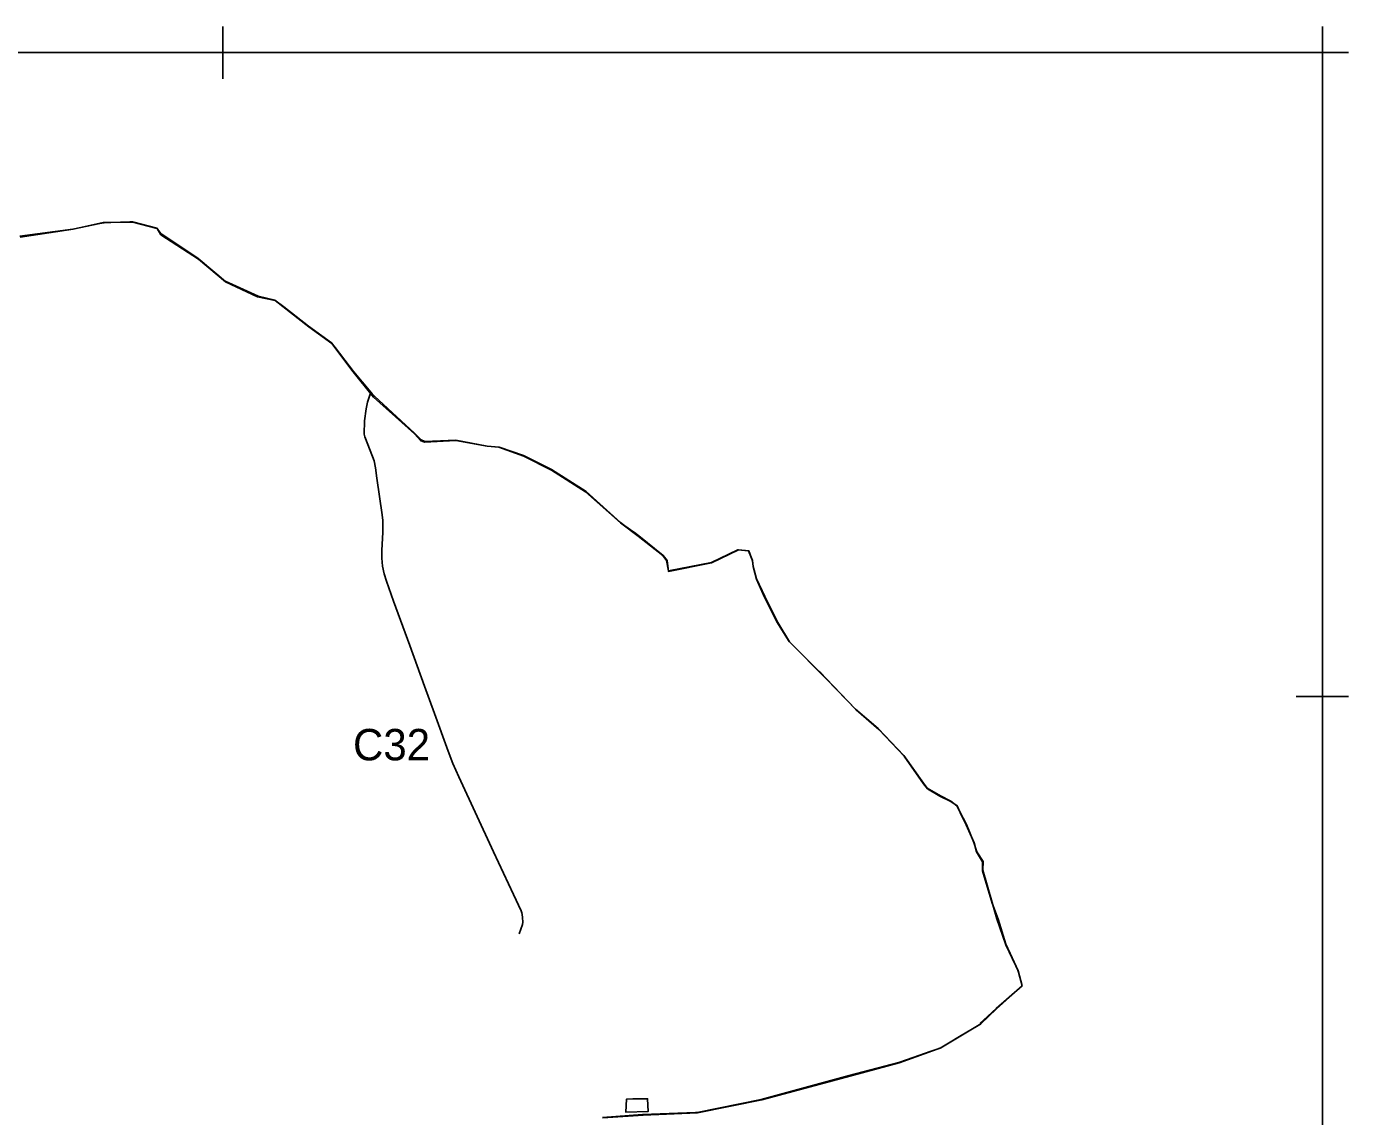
# Model space of a CAD drawing. Extents: x -478490 to -472450, y -1118050 to -1109550.
# Drawn here: x -474975 to -472450, y -1111633 to -1109550 of the extents above; entities that cross this region are included whole.
import ezdxf

# ---------------------------------------------------------------- set-up
doc = ezdxf.new("R2010")
doc.units = 0
for name, color, linetype in [('hranice kú', 7, 'Continuous'), ('Implicitní', 7, 'Continuous'), ('ObPÚ', 7, 'Continuous')]:
    doc.layers.add(name, color=color, linetype=linetype)

msp = doc.modelspace()

# ---------------------------------------------------------------- linework, layer by layer
at = {"layer": 'hranice kú'}
for p, q in [((-474828.5, -1109924.9), (-474886, -1109937.7)), ((-474772, -1109923.9), (-474828.5, -1109924.9)), ((-474725.6, -1109936), (-474772, -1109923.9)), ((-474886, -1109937.7), (-474987.2, -1109952.5)), ((-474718.2, -1109948.1), (-474725.6, -1109936)), ((-474646.3, -1109994.8), (-474718.2, -1109948.1)), ((-474595.2, -1110038.2), (-474646.3, -1109994.8)), ((-474533.5, -1110066.7), (-474595.2, -1110038.2)), ((-474500.2, -1110073.4), (-474533.5, -1110066.7)), ((-474436, -1110123.8), (-474500.2, -1110073.4)), ((-474392.1, -1110155.8), (-474436, -1110123.8)), ((-474351.1, -1110210.2), (-474392.1, -1110155.8)), ((-474312.1, -1110258.1), (-474351.1, -1110210.2)), ((-474234.1, -1110328.4), (-474312.1, -1110258.1)), ((-474222.7, -1110341.2), (-474234.1, -1110328.4)), ((-474214.6, -1110344.2), (-474222.7, -1110341.2)), ((-474155.1, -1110341.5), (-474214.6, -1110344.2)), ((-474095.2, -1110352.2), (-474155.1, -1110341.5)), ((-474072.7, -1110354.2), (-474095.2, -1110352.2)), ((-474025.3, -1110371.1), (-474072.7, -1110354.2)), ((-473972.5, -1110398), (-474025.3, -1110371.1)), ((-473907.3, -1110439), (-473972.5, -1110398)), ((-473840.6, -1110498.6), (-473907.3, -1110439)), ((-473807, -1110524.1), (-473840.6, -1110498.6)), ((-473760, -1110561.1), (-473807, -1110524.1)), ((-473752.6, -1110570.7), (-473760, -1110561.1)), ((-473616.5, -1110549.9), (-473666.9, -1110574.4)), ((-473595.9, -1110552.2), (-473616.5, -1110549.9)), ((-473588.6, -1110570.3), (-473595.9, -1110552.2)), ((-473748.8, -1110590.3), (-473752.6, -1110570.7)), ((-473666.9, -1110574.4), (-473748.8, -1110590.3)), ((-473587, -1110582.1), (-473588.6, -1110570.3)), ((-473581.1, -1110606.2), (-473587, -1110582.1)), ((-473565.4, -1110640.2), (-473581.1, -1110606.2)), ((-473541.9, -1110687.9), (-473565.4, -1110640.2)), ((-473518.4, -1110725.3), (-473541.9, -1110687.9)), ((-473447.1, -1110796.9), (-473518.4, -1110725.3)), ((-473390.3, -1110855.8), (-473447.1, -1110796.9)), ((-473347.2, -1110893.3), (-473390.3, -1110855.8)), ((-473299.1, -1110944.4), (-473347.2, -1110893.3)), ((-473261.8, -1110997.2), (-473299.1, -1110944.4)), ((-473254.4, -1111006.6), (-473261.8, -1110997.2)), ((-473230.6, -1111020.7), (-473254.4, -1111006.6)), ((-473209.4, -1111030.8), (-473230.6, -1111020.7)), ((-473197.9, -1111039.5), (-473209.4, -1111030.8)), ((-473191.9, -1111051.7), (-473197.9, -1111039.5)), ((-473180.1, -1111075.5), (-473191.9, -1111051.7)), ((-473165, -1111109.9), (-473180.1, -1111075.5)), ((-473160.6, -1111127.4), (-473165, -1111109.9)), ((-473148.9, -1111145.9), (-473160.6, -1111127.4)), ((-473149.2, -1111163.1), (-473148.9, -1111145.9)), ((-473130.7, -1111224.9), (-473149.2, -1111163.1)), ((-473119.6, -1111255.5), (-473130.7, -1111224.9)), ((-473104.5, -1111303.7), (-473119.6, -1111255.5)), ((-473092.7, -1111329.3), (-473104.5, -1111303.7)), ((-473081.3, -1111354.2), (-473092.7, -1111329.3)), ((-473073.6, -1111382.8), (-473081.3, -1111354.2)), ((-473122.6, -1111427.2), (-473073.6, -1111382.8)), ((-473152.2, -1111455.7), (-473122.6, -1111427.2)), ((-473228.9, -1111501.8), (-473152.2, -1111455.7)), ((-473308.3, -1111530.5), (-473228.9, -1111501.8)), ((-473402.8, -1111555.4), (-473308.3, -1111530.5)), ((-473570.6, -1111601.1), (-473402.8, -1111555.4)), ((-473693.7, -1111625.7), (-473570.6, -1111601.1)), ((-473874.4, -1111635.4), (-473797.2, -1111630.4)), ((-473797.2, -1111630.4), (-473693.7, -1111625.7))]:
    msp.add_line(p, q, dxfattribs=at)
at = {"layer": 'Implicitní'}
for p, q in [((-474600.1, -1109550.1), (-474600.1, -1109650.1)), ((-474600.1, -1109550.1), (-474600.1, -1109650.1)), ((-474600.1, -1109550.1), (-474600.1, -1109650.1)), ((-474600.1, -1109550.1), (-474600.1, -1109650.1)), ((-474600.1, -1109550.1), (-474600.1, -1109650.1)), ((-474600.1, -1109550.1), (-474600.1, -1109650.1)), ((-474600.1, -1109550.1), (-474600.1, -1109650.1)), ((-474600.1, -1109550.1), (-474600.1, -1109650.1)), ((-474600.1, -1109550.1), (-474600.1, -1109650.1)), ((-474600.1, -1109550.1), (-474600.1, -1109650.1)), ((-474600.1, -1109550.1), (-474600.1, -1109650.1)), ((-474600.1, -1109550.1), (-474600.1, -1109650.1)), ((-474600.1, -1109550.1), (-474600.1, -1109650.1)), ((-474600.1, -1109550.1), (-474600.1, -1109650.1)), ((-474600.1, -1109550.1), (-474600.1, -1109650.1)), ((-474600.1, -1109550.1), (-474600.1, -1109650.1)), ((-474600.1, -1109550.1), (-474600.1, -1109650.1)), ((-474600.1, -1109550.1), (-474600.1, -1109650.1)), ((-474600.1, -1109550.1), (-474600.1, -1109650.1)), ((-474600.1, -1109550.1), (-474600.1, -1109650.1)), ((-474600.1, -1109550.1), (-474600.1, -1109650.1)), ((-474600.1, -1109550.1), (-474600.1, -1109650.1)), ((-474600.1, -1109550.1), (-474600.1, -1109650.1)), ((-474600.1, -1109550.1), (-474600.1, -1109650.1)), ((-474600.1, -1109550.1), (-474600.1, -1109650.1)), ((-474600.1, -1109550.1), (-474600.1, -1109650.1)), ((-474600.1, -1109550.1), (-474600.1, -1109650.1)), ((-474600.1, -1109550.1), (-474600.1, -1109650.1)), ((-474600.1, -1109550.1), (-474600.1, -1109650.1)), ((-474600.1, -1109550.1), (-474600.1, -1109650.1)), ((-474600.1, -1109550.1), (-474600.1, -1109650.1)), ((-474600.1, -1109550.1), (-474600.1, -1109650.1)), ((-474600.1, -1109550.1), (-474600.1, -1109650.1)), ((-474600.1, -1109550.1), (-474600.1, -1109650.1)), ((-474600.1, -1109550.1), (-474600.1, -1109650.1)), ((-474600.1, -1109550.1), (-474600.1, -1109650.1)), ((-474600.1, -1109550.1), (-474600.1, -1109650.1)), ((-474600.1, -1109550.1), (-474600.1, -1109650.1)), ((-474600.1, -1109550.1), (-474600.1, -1109650.1)), ((-474600.1, -1109550.1), (-474600.1, -1109650.1)), ((-474600.1, -1109550.1), (-474600.1, -1109650.1)), ((-474600.1, -1109550.1), (-474600.1, -1109650.1)), ((-474600.1, -1109550.1), (-474600.1, -1109650.1)), ((-474600.1, -1109550.1), (-474600.1, -1109650.1)), ((-474600.1, -1109550.1), (-474600.1, -1109650.1)), ((-474600.1, -1109550.1), (-474600.1, -1109650.1)), ((-474600.1, -1109550.1), (-474600.1, -1109650.1)), ((-474600.1, -1109550.1), (-474600.1, -1109650.1)), ((-474600.1, -1109550.1), (-474600.1, -1109650.1)), ((-474600.1, -1109550.1), (-474600.1, -1109650.1)), ((-474600.1, -1109550.1), (-474600.1, -1109650.1)), ((-472500.1, -1109550.1), (-472500.1, -1109650.1)), ((-472500.1, -1109550.1), (-472500.1, -1109650.1)), ((-472500.1, -1109550.1), (-472500.1, -1109650.1)), ((-472500.1, -1109550.1), (-472500.1, -1109650.1)), ((-472500.1, -1109550.1), (-472500.1, -1109650.1)), ((-472500.1, -1109550.1), (-472500.1, -1109650.1)), ((-472500.1, -1109550.1), (-472500.1, -1109650.1)), ((-472500.1, -1109550.1), (-472500.1, -1109650.1)), ((-472500.1, -1109550.1), (-472500.1, -1109650.1)), ((-472500.1, -1109550.1), (-472500.1, -1109650.1)), ((-472500.1, -1109550.1), (-472500.1, -1109650.1)), ((-472500.1, -1109550.1), (-472500.1, -1109650.1)), ((-472500.1, -1109550.1), (-472500.1, -1109650.1)), ((-472500.1, -1109550.1), (-472500.1, -1109650.1)), ((-472500.1, -1109550.1), (-472500.1, -1109650.1)), ((-472500.1, -1109550.1), (-472500.1, -1109650.1)), ((-472500.1, -1109550.1), (-472500.1, -1109650.1)), ((-472500.1, -1109550.1), (-472500.1, -1109650.1)), ((-472500.1, -1109550.1), (-472500.1, -1109650.1)), ((-472500.1, -1109550.1), (-472500.1, -1109650.1)), ((-474550.1, -1109600.1), (-474650.1, -1109600.1)), ((-474550.1, -1109600.1), (-474650.1, -1109600.1)), ((-474550.1, -1109600.1), (-474650.1, -1109600.1)), ((-474550.1, -1109600.1), (-474650.1, -1109600.1)), ((-474550.1, -1109600.1), (-474650.1, -1109600.1)), ((-474550.1, -1109600.1), (-474650.1, -1109600.1)), ((-474550.1, -1109600.1), (-474650.1, -1109600.1)), ((-474550.1, -1109600.1), (-474650.1, -1109600.1)), ((-474550.1, -1109600.1), (-474650.1, -1109600.1)), ((-474550.1, -1109600.1), (-474650.1, -1109600.1)), ((-474550.1, -1109600.1), (-474650.1, -1109600.1)), ((-474550.1, -1109600.1), (-474650.1, -1109600.1)), ((-474550.1, -1109600.1), (-474650.1, -1109600.1)), ((-474550.1, -1109600.1), (-474650.1, -1109600.1)), ((-474550.1, -1109600.1), (-474650.1, -1109600.1)), ((-474550.1, -1109600.1), (-474650.1, -1109600.1)), ((-474550.1, -1109600.1), (-474650.1, -1109600.1)), ((-474550.1, -1109600.1), (-474650.1, -1109600.1)), ((-474550.1, -1109600.1), (-474650.1, -1109600.1)), ((-474550.1, -1109600.1), (-474650.1, -1109600.1)), ((-474550.1, -1109600.1), (-474650.1, -1109600.1)), ((-474550.1, -1109600.1), (-474650.1, -1109600.1)), ((-474550.1, -1109600.1), (-474650.1, -1109600.1)), ((-474550.1, -1109600.1), (-474650.1, -1109600.1)), ((-474550.1, -1109600.1), (-474650.1, -1109600.1)), ((-474550.1, -1109600.1), (-474650.1, -1109600.1)), ((-474550.1, -1109600.1), (-474650.1, -1109600.1)), ((-474550.1, -1109600.1), (-474650.1, -1109600.1)), ((-474550.1, -1109600.1), (-474650.1, -1109600.1)), ((-474550.1, -1109600.1), (-474650.1, -1109600.1)), ((-474550.1, -1109600.1), (-474650.1, -1109600.1)), ((-474550.1, -1109600.1), (-474650.1, -1109600.1)), ((-474550.1, -1109600.1), (-474650.1, -1109600.1)), ((-474550.1, -1109600.1), (-474650.1, -1109600.1)), ((-474550.1, -1109600.1), (-474650.1, -1109600.1)), ((-474550.1, -1109600.1), (-474650.1, -1109600.1)), ((-474550.1, -1109600.1), (-474650.1, -1109600.1)), ((-474550.1, -1109600.1), (-474650.1, -1109600.1)), ((-474550.1, -1109600.1), (-474650.1, -1109600.1)), ((-474550.1, -1109600.1), (-474650.1, -1109600.1)), ((-474550.1, -1109600.1), (-474650.1, -1109600.1)), ((-474550.1, -1109600.1), (-474650.1, -1109600.1)), ((-474550.1, -1109600.1), (-474650.1, -1109600.1)), ((-474550.1, -1109600.1), (-474650.1, -1109600.1)), ((-474550.1, -1109600.1), (-474650.1, -1109600.1)), ((-474550.1, -1109600.1), (-474650.1, -1109600.1)), ((-474550.1, -1109600.1), (-474650.1, -1109600.1)), ((-474550.1, -1109600.1), (-474650.1, -1109600.1)), ((-474550.1, -1109600.1), (-474650.1, -1109600.1)), ((-474550.1, -1109600.1), (-474650.1, -1109600.1)), ((-472450.1, -1109600.1), (-472550.1, -1109600.1)), ((-472450.1, -1109600.1), (-472550.1, -1109600.1)), ((-472450.1, -1109600.1), (-472550.1, -1109600.1)), ((-472450.1, -1109600.1), (-472550.1, -1109600.1)), ((-472450.1, -1109600.1), (-472550.1, -1109600.1)), ((-472450.1, -1109600.1), (-472550.1, -1109600.1)), ((-472450.1, -1109600.1), (-472550.1, -1109600.1)), ((-472450.1, -1109600.1), (-472550.1, -1109600.1)), ((-472450.1, -1109600.1), (-472550.1, -1109600.1)), ((-472450.1, -1109600.1), (-472550.1, -1109600.1)), ((-472450.1, -1109600.1), (-472550.1, -1109600.1)), ((-472450.1, -1109600.1), (-472550.1, -1109600.1)), ((-472450.1, -1109600.1), (-472550.1, -1109600.1)), ((-472450.1, -1109600.1), (-472550.1, -1109600.1)), ((-472450.1, -1109600.1), (-472550.1, -1109600.1)), ((-472450.1, -1109600.1), (-472550.1, -1109600.1)), ((-472450.1, -1109600.1), (-472550.1, -1109600.1)), ((-472450.1, -1109600.1), (-472550.1, -1109600.1)), ((-472450.1, -1109600.1), (-472550.1, -1109600.1)), ((-472450.1, -1109600.1), (-472550.1, -1109600.1)), ((-472500.1, -1110780.1), (-472500.1, -1110880.1)), ((-472500.1, -1110780.1), (-472500.1, -1110880.1)), ((-472500.1, -1110780.1), (-472500.1, -1110880.1)), ((-472500.1, -1110780.1), (-472500.1, -1110880.1)), ((-472500.1, -1110780.1), (-472500.1, -1110880.1)), ((-472500.1, -1110780.1), (-472500.1, -1110880.1)), ((-472500.1, -1110780.1), (-472500.1, -1110880.1)), ((-472500.1, -1110780.1), (-472500.1, -1110880.1)), ((-472500.1, -1110780.1), (-472500.1, -1110880.1)), ((-472500.1, -1110780.1), (-472500.1, -1110880.1)), ((-472450.1, -1110830.1), (-472550.1, -1110830.1)), ((-472450.1, -1110830.1), (-472550.1, -1110830.1)), ((-472450.1, -1110830.1), (-472550.1, -1110830.1)), ((-472450.1, -1110830.1), (-472550.1, -1110830.1)), ((-472450.1, -1110830.1), (-472550.1, -1110830.1)), ((-472450.1, -1110830.1), (-472550.1, -1110830.1)), ((-472450.1, -1110830.1), (-472550.1, -1110830.1)), ((-472450.1, -1110830.1), (-472550.1, -1110830.1)), ((-472450.1, -1110830.1), (-472550.1, -1110830.1)), ((-472450.1, -1110830.1), (-472550.1, -1110830.1))]:
    msp.add_line(p, q, dxfattribs=at)
msp.add_lwpolyline([(-478440.1, -1118000.1), (-472500.1, -1118000.1), (-472500.1, -1109600.1), (-478440.1, -1109600.1)], close=True, dxfattribs=at)
msp.add_lwpolyline([(-474317.1, -1110249), (-474323.4, -1110268), (-474326.2, -1110280.7), (-474329.6, -1110303.5), (-474330.2, -1110328.9), (-474328.9, -1110334.4), (-474318.8, -1110360.4), (-474311.3, -1110380), (-474308.3, -1110393.2), (-474306.2, -1110413.1), (-474295.4, -1110483.4), (-474294.5, -1110494.2), (-474294.4, -1110516.4), (-474296.3, -1110551.1), (-474296.3, -1110566.2), (-474294.9, -1110581.1), (-474291.9, -1110595.9), (-474287.5, -1110610.2), (-474273.8, -1110648), (-474243, -1110732.9), (-474214.9, -1110810.4), (-474195.9, -1110863), (-474169.8, -1110934.9), (-474161, -1110958.2), (-474149.5, -1110983.8), (-474082.9, -1111127), (-474044.9, -1111208.7), (-474030.3, -1111240.1), (-474029, -1111243.5), (-474028.1, -1111246.7), (-474027.5, -1111252.8), (-474027.2, -1111261.5), (-474027.8, -1111265.9), (-474030.6, -1111274.7), (-474033.9, -1111284)], dxfattribs=at)
at = {"layer": 'ObPÚ'}
for points in [[(-474987.5, -1109951), (-474886.4, -1109937.2), (-474835.2, -1109926.7), (-474826.9, -1109925), (-474813.9, -1109924.6), (-474777.6, -1109923.6), (-474775.1, -1109923.6), (-474772.3, -1109923.5)], [(-474772.3, -1109923.5), (-474725.8, -1109935.5), (-474718.4, -1109945.5), (-474708.6, -1109952.2), (-474646.9, -1109993.6), (-474635.8, -1110003), (-474630.5, -1110007.4), (-474607.9, -1110026.4), (-474597.8, -1110034.9), (-474595.5, -1110036.8), (-474532.2, -1110065.4), (-474500.7, -1110072.8), (-474483.7, -1110086), (-474436.4, -1110122.7), (-474392.2, -1110154.3), (-474385.2, -1110163.5), (-474350.2, -1110209.6), (-474320.4, -1110245), (-474314.7, -1110251.8), (-474310.6, -1110256.4), (-474234.2, -1110327.1), (-474221.3, -1110340), (-474214.3, -1110343), (-474154.8, -1110340.7), (-474095.4, -1110351.7), (-474072.2, -1110354), (-474026, -1110369.9), (-473972.3, -1110396.9), (-473906.1, -1110438.9), (-473840.6, -1110497.7), (-473832.2, -1110504.2), (-473830.5, -1110505.3), (-473821.5, -1110511.8), (-473813.9, -1110517.2), (-473805.4, -1110523.4), (-473759.3, -1110560.8), (-473751.6, -1110570.6), (-473749, -1110591.2), (-473666.9, -1110574.8), (-473615.4, -1110550.1), (-473595.3, -1110552.3), (-473588.2, -1110570.8), (-473587, -1110581.7), (-473580.8, -1110605.5), (-473565.2, -1110639.4), (-473540.1, -1110688.9), (-473517.9, -1110725.6), (-473460.9, -1110782.6), (-473458.1, -1110785.3), (-473448, -1110796.1), (-473392, -1110854.4), (-473348.2, -1110891.4), (-473299.5, -1110943.1), (-473262, -1110995.9), (-473255, -1111005.5), (-473229.4, -1111020.1), (-473209.5, -1111030.1), (-473198.2, -1111039.4), (-473192.6, -1111050.5), (-473179.5, -1111074.9), (-473165.6, -1111109), (-473160.2, -1111126.9), (-473147.9, -1111145.8), (-473148.5, -1111162.4), (-473131, -1111223.7), (-473121.6, -1111255.3), (-473104.7, -1111304.7), (-473092.8, -1111330), (-473085.6, -1111345), (-473081.6, -1111353.4), (-473080.7, -1111357.3), (-473073.7, -1111383.2), (-473122.8, -1111426.6), (-473147.5, -1111448.9), (-473153.4, -1111454.2), (-473153.1, -1111456.1), (-473157.3, -1111458.6), (-473193.3, -1111480.1), (-473214.3, -1111492.6), (-473230.3, -1111502), (-473249.2, -1111508.7), (-473268.9, -1111515.5), (-473294.2, -1111524.5), (-473309.1, -1111529.7), (-473403.8, -1111554.6), (-473571.9, -1111600.5), (-473694.2, -1111625.2), (-473697.3, -1111625.4), (-473798.5, -1111629.2), (-473875.2, -1111634.7)], [(-473788.9, -1111598.7), (-473787.6, -1111623.1), (-473830.3, -1111624.7), (-473829, -1111599.5), (-473817, -1111599.2), (-473799.7, -1111598.8), (-473788.9, -1111598.7)], [(-473799.7, -1111598.8), (-473817, -1111599.2), (-473829, -1111599.5), (-473830.3, -1111624.7), (-473787.6, -1111623.1), (-473788.9, -1111598.7), (-473799.7, -1111598.8)]]:
    msp.add_lwpolyline(points, dxfattribs=at)

# ---------------------------------------------------------------- texts
at = {"layer": 'Implicitní'}
msp.add_text('C32', height=60, dxfattribs=at).set_placement((-474351.4, -1110952.3))

doc.saveas('drawing.dxf')
